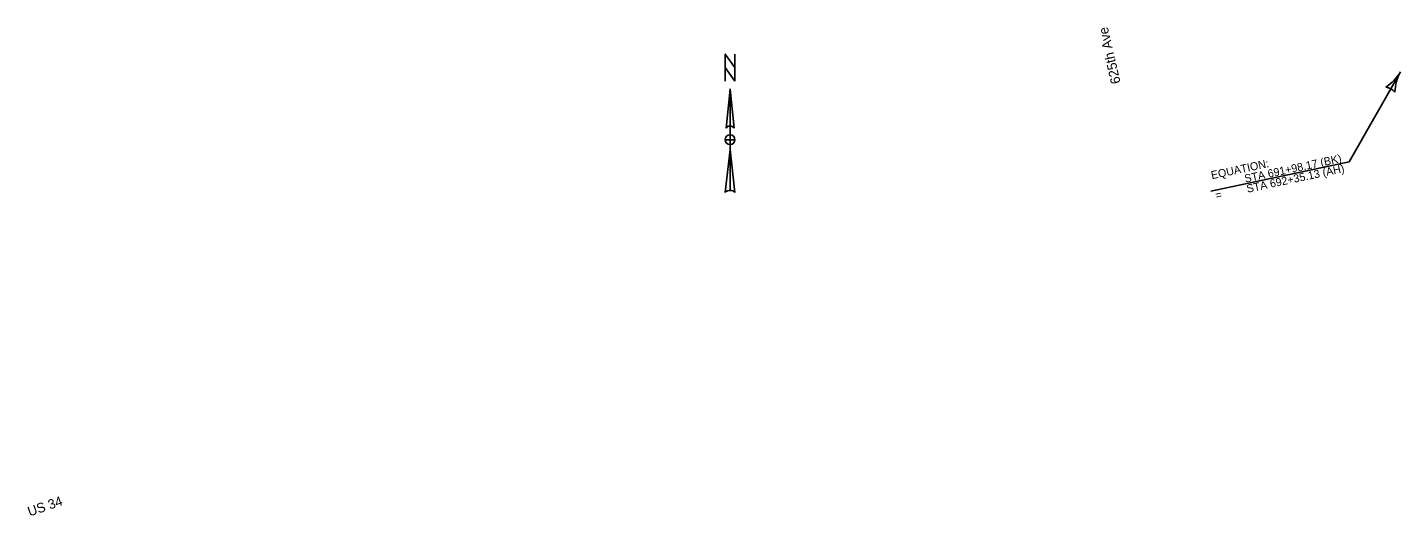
# Model space of a CAD drawing. Extents: x 22712865 to 22760106, y 6235088 to 6238602.
# Drawn here: x 22743699 to 22746376, y 6237059 to 6238011 of the extents above; entities that cross this region are included whole.
import ezdxf

# ---------------------------------------------------------------- set-up
doc = ezdxf.new("R2010")
doc.units = 0
for name, color, linetype in [('Contours Major', 7, 'Continuous'), ('Default', 7, 'Continuous'), ('dsnTextOdd', 7, 'Continuous')]:
    doc.layers.add(name, color=color, linetype=linetype)

msp = doc.modelspace()

# ---------------------------------------------------------------- linework, layer by layer
at = {"layer": 'Contours Major'}
msp.add_lwpolyline([(22746376.2, 6237924.7), (22746276.3, 6237749.1), (22746006.5, 6237691.5)], dxfattribs=at)
for centre, radius, start, end in [((22746302.3, 6237966.8), 85, 302.2932, 330.3657), ((22746450.1, 6237882.7), 85, 150.3657, 178.4382), ((22746340.9, 6237862.8), 32.8, 42.6323, 78.099)]:
    msp.add_arc(centre, radius, start, end, dxfattribs=at)
at = {"layer": 'dsnTextOdd'}
for p, q in [((22745068.9, 6237890.9), (22745076.5, 6237814.8)), ((22745068.9, 6237890.9), (22745068.9, 6237693.1)), ((22745061.3, 6237814.8), (22745061.3, 6237814.8)), ((22745061.6, 6237815.5), (22745063, 6237817.1)), ((22745059.4, 6237689.3), (22745068.9, 6237773)), ((22745068.9, 6237782.5), (22745068.9, 6237782.5))]:
    msp.add_line(p, q, dxfattribs=at)
msp.add_lwpolyline([(22745078.4, 6237906.1), (22745059.4, 6237932.7), (22745059.4, 6237959.3), (22745078.4, 6237932.7)], close=True, dxfattribs=at)
for points in [[(22745059.4, 6237906.1), (22745059.4, 6237959.3), (22745078.4, 6237932.7), (22745078.4, 6237959.3)], [(22745061.3, 6237814.8), (22745068.9, 6237890.9), (22745068.9, 6237818.6)], [(22745078.4, 6237792), (22745068.9, 6237792), (22745068.9, 6237801.5)], [(22745068.9, 6237782.5), (22745068.9, 6237792), (22745059.4, 6237792)], [(22745068.9, 6237693.1), (22745068.9, 6237773), (22745078.4, 6237689.3)]]:
    msp.add_lwpolyline(points, dxfattribs=at)
for centre, radius, start, end in [((22745068.9, 6237792), 9.51, 90, 180), ((22745068.9, 6237809.1), 9.51, 90.0204, 143.1257), ((22745068.9, 6237809.1), 9.5, 36.8481, 90.0218), ((22745068.9, 6237792), 9.51, 0, 90), ((22745068.9, 6237792), 9.51, 180, 270), ((22745068.9, 6237792), 9.51, 270, 360), ((22745068.9, 6237679.3), 13.8, 89.9894, 133.619), ((22745068.9, 6237679.3), 13.8, 46.4021, 90.0006)]:
    msp.add_arc(centre, radius, start, end, dxfattribs=at)

# ---------------------------------------------------------------- texts
at = {"layer": 'Contours Major'}
for s, height, p in [('EQUATION:', 15.6, (22746008.4, 6237714.9)), ('STA 691+98.17 (BK)', 15.601, (22746073.6, 6237708.2)), ('STA 692+35.13 (AH)', 15.601, (22746077.8, 6237688.5)), ('=', 15.6, (22746016.8, 6237675.4))]:
    msp.add_text(s, height=height, rotation=12.0545, dxfattribs=at).set_placement(p)
at = {"layer": 'Default'}
for s, rotation, p in [('625th Ave', 102.9662, (22745830.5, 6237903.3)), ('US 34', 19.0497, (22743703.1, 6237056.6))]:
    msp.add_text(s, height=18.75, rotation=rotation, dxfattribs=at).set_placement(p)

doc.saveas('drawing.dxf')
